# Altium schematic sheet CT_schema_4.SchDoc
size 334 x 183 mm
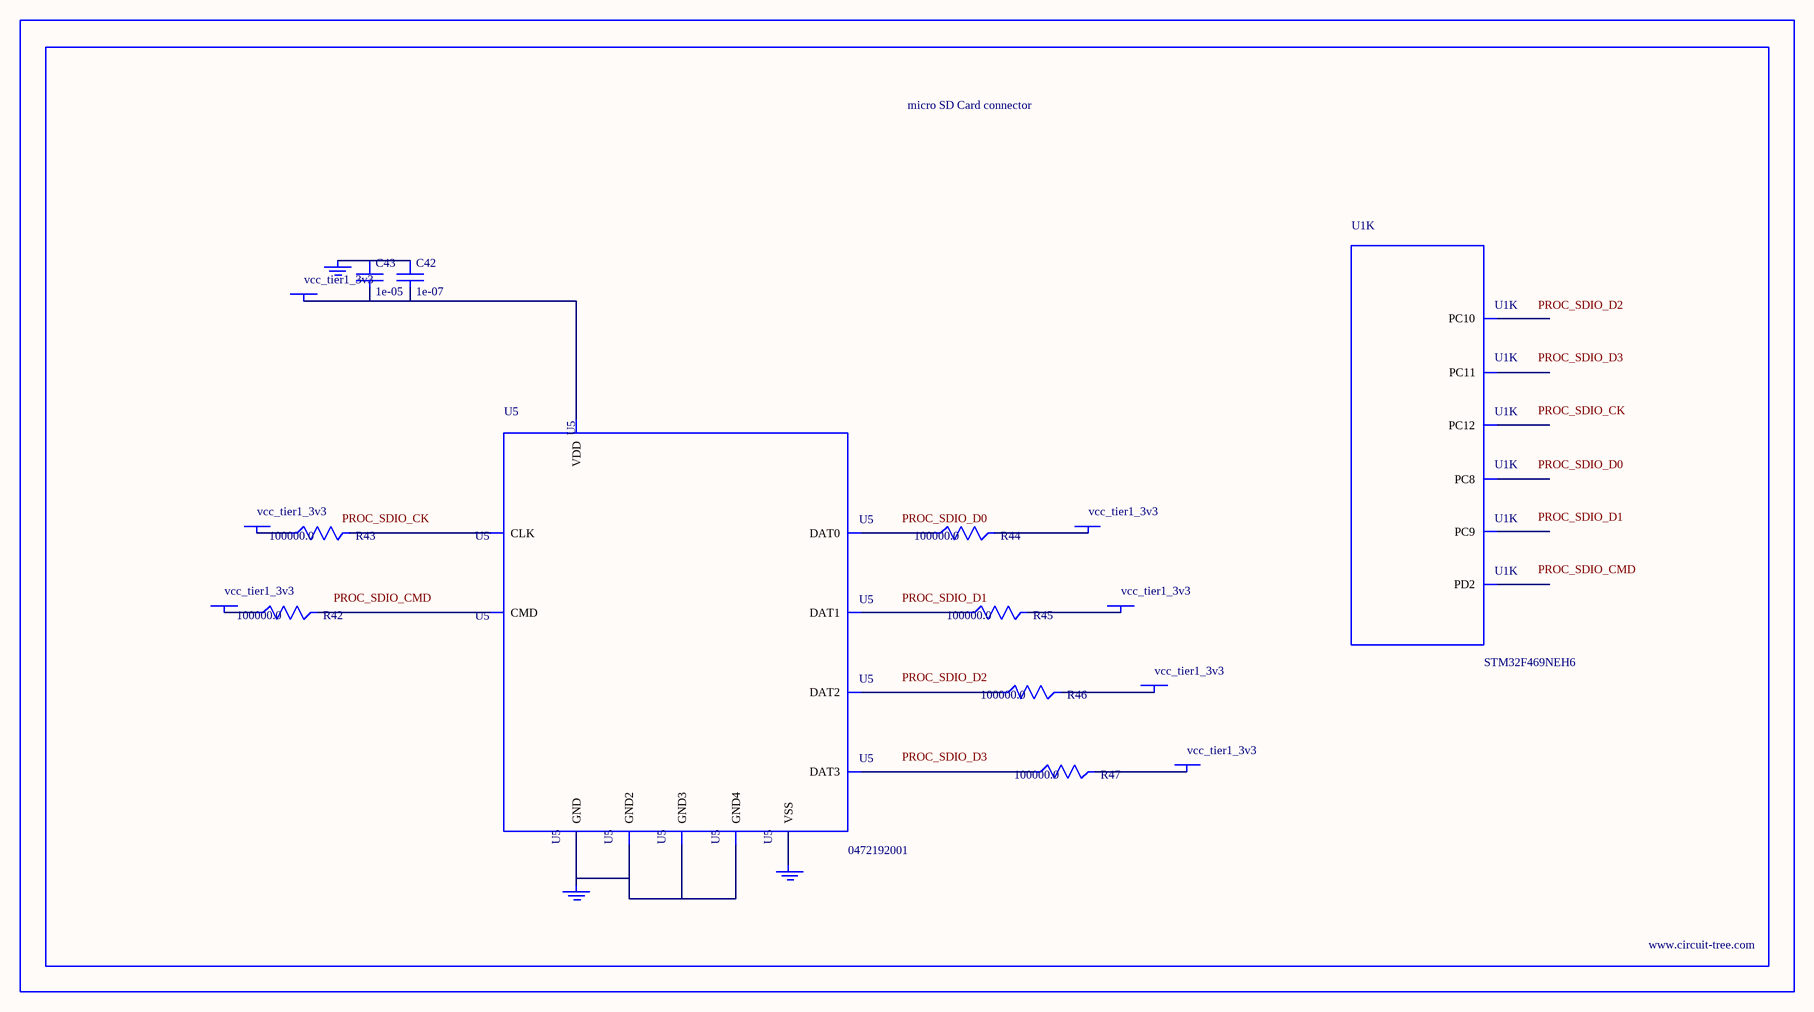
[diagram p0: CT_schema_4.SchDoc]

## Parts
BORDER3  (no value)
C42  1e-07  [C0402]
C43  1e-05  [C0805]
GND_INSTANCE_3_0  (no value)
GND_INSTANCE_3_1  (no value)
GND_INSTANCE_3_2  (no value)
POWER_INSTANCE_3_0  vcc_tier1_3v3
POWER_INSTANCE_3_1  vcc_tier1_3v3
POWER_INSTANCE_3_2  vcc_tier1_3v3
POWER_INSTANCE_3_3  vcc_tier1_3v3
POWER_INSTANCE_3_4  vcc_tier1_3v3
POWER_INSTANCE_3_5  vcc_tier1_3v3
POWER_INSTANCE_3_6  vcc_tier1_3v3
R42  100000.0  [R0603]
R43  100000.0  [R0603]
R44  100000.0  [R0603]
R45  100000.0  [R0603]
R46  100000.0  [R0603]
R47  100000.0  [R0603]
U1  STM32F469NEH6  [TFBGA216]  (part K of 17)
U5  0472192001  [MOLEX_47219-2001]

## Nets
NetC42_1: C42.1 C43.1 GND_INSTANCE_3_0.0(GND)
NetC42_2: C42.2 C43.2 POWER_INSTANCE_3_3.0(PWR) U5.4(VDD)
NetGND_INSTANCE_3_1_0: GND_INSTANCE_3_1.0(GND) U5.6(VSS)
NetGND_INSTANCE_3_2_0: GND_INSTANCE_3_2.0(GND) U5.G1(GND) U5.G2(GND2) U5.G3(GND3) U5.G4(GND4)
NetPOWER_INSTANCE_3_0_0: POWER_INSTANCE_3_0.0(PWR) R46.2
NetPOWER_INSTANCE_3_1_0: POWER_INSTANCE_3_1.0(PWR) R47.2
NetPOWER_INSTANCE_3_2_0: POWER_INSTANCE_3_2.0(PWR) R42.1
NetPOWER_INSTANCE_3_4_0: POWER_INSTANCE_3_4.0(PWR) R43.1
NetPOWER_INSTANCE_3_5_0: POWER_INSTANCE_3_5.0(PWR) R44.2
NetPOWER_INSTANCE_3_6_0: POWER_INSTANCE_3_6.0(PWR) R45.2
NetR42_2: R42.2 U5.3(CMD)
NetR43_2: R43.2 U5.5(CLK)
NetR44_1: R44.1 U5.7(DAT0)
NetR45_1: R45.1 U5.8(DAT1)
NetR46_1: R46.1 U5.1(DAT2)
NetR47_1: R47.1 U5.2(DAT3)

Not connected (* = marked no-connect by the designer): U1 A12(PC12) B13(PC11) B14(PC10) D12(PD2) F14(PC9) G14(PC8)

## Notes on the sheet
- Labels drawn without touching a wire or pin: PROC_SDIO_CK, PROC_SDIO_CMD, PROC_SDIO_D0, PROC_SDIO_D1, PROC_SDIO_D2, PROC_SDIO_D3

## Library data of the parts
BORDER3 = BORDER_PAGE3
C42 = C0402C104K3RACTU
C43 = C0805C106K8RACTU
GND_INSTANCE_3_0-GND_INSTANCE_3_2 = GND
POWER_INSTANCE_3_0-POWER_INSTANCE_3_6 = PWR
R42-R47 = RC0603JR-07100KL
